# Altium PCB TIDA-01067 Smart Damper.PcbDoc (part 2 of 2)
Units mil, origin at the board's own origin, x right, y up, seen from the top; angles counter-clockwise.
Board outline 4000 x 3450 mil, 4 copper layers (Top Layer, Signal Layer 1, Signal Layer 2, Bottom Layer), stack 63 mil thick; 101 components, 44 nets, 285 pads, 617 vias.
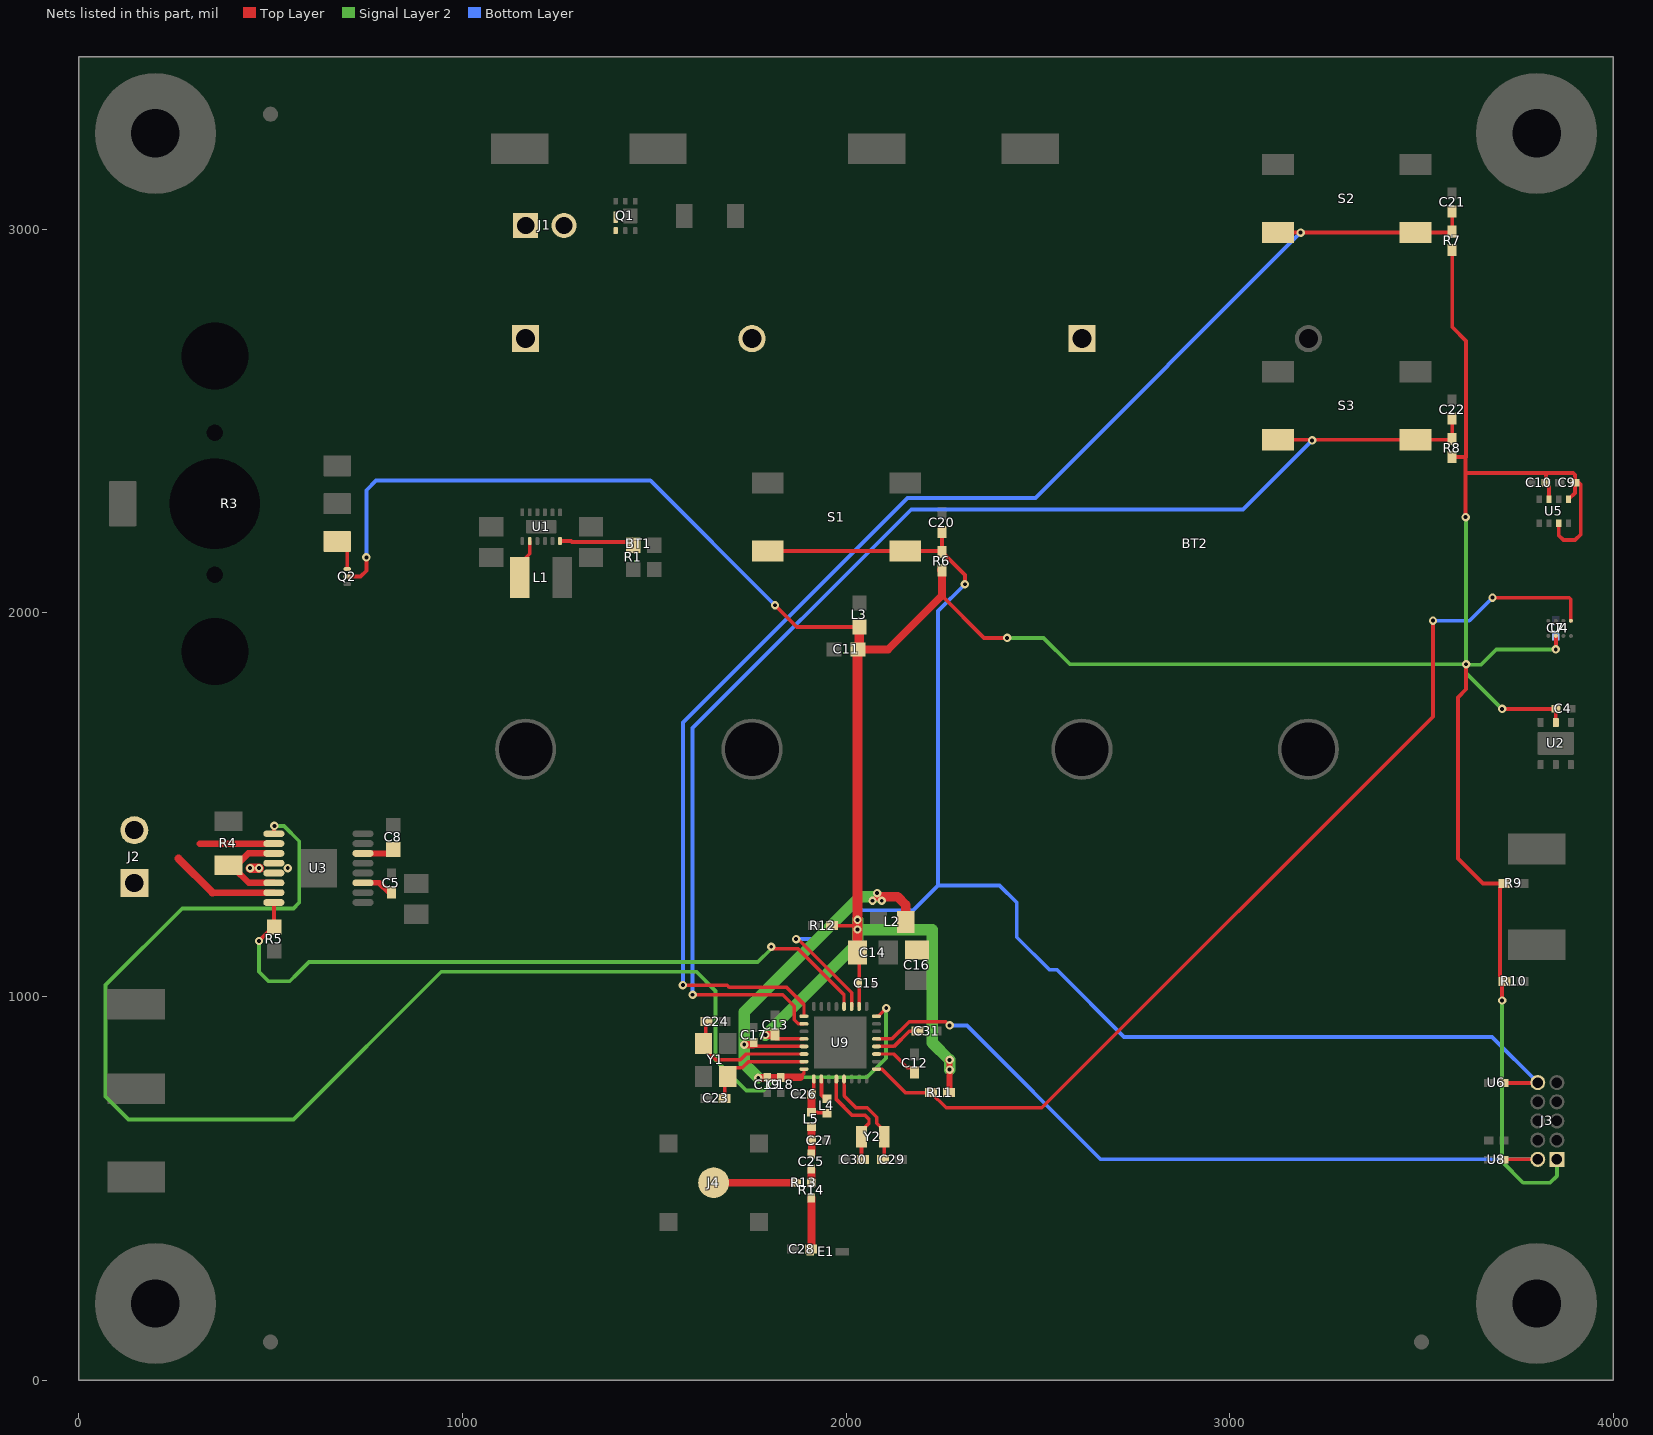
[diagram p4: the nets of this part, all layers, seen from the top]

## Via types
v1: diameter 22, hole 10, Top Layer to Bottom Layer, tented both sides, 560 vias
v2: diameter 19.68, hole 7.87, Top Layer to Bottom Layer, 29 vias
v3: diameter 22, hole 10, Top Layer to Bottom Layer, 27 vias
v4: diameter 19, hole 8, Top Layer to Bottom Layer, tented both sides, 1 vias

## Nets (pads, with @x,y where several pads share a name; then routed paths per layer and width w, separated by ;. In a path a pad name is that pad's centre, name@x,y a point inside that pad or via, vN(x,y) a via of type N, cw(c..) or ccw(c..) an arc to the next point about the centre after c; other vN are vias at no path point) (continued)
JTAG_TMS: J3.2 U8.1 U9.13 | length 1979.2
  Top Layer w9: U9.13@2079.49,889.84 2119.84,889.84 2165,935 2260,935 v1(2270,925)
  Top Layer w10: U8.1@3714.69,576 J3.2@3803,576
  Bottom Layer w10: v1(2270,925) 2315,925 2664,576 J3.2@3803,576
NDRDY_HDC: R11.1 U4.D2 U9.9 | length 2606.9
  Top Layer w9: U9.9@2079.49,811.1 2093.9,811.1 2155,750 R11.1@2221.38,750 2261.38,710 2510,710 3530,1730 ; v3(3685,2040) 3885,2040 3889.53,2035.47 U4.D2@3889.53,1979.69
  Top Layer w10: 3530,1730 v3(3530,1980)
  Bottom Layer w9: v3(3530,1980) 3625,1980 v3(3685,2040)
NetBT1_2: BT1.2 BT2.1
NetC5_1: C5.1 U3.11 | length 79.9
  Top Layer w15: U3.11@741.14,1296.61 783.39,1296.61 C5.1@810,1270
NetC8_1: C8.1 U3.14 | length 87.2
  Top Layer w15: U3.14@741.14,1373.39 811.89,1373.39 C8.1@823.5,1385
NetC23_2: C23.2 U9.31 Y1.3 | length 289.1
  Top Layer w9: Y1.3@1680,815 1730,815 1745.79,830.79 U9.31@1890.51,830.79 ; C23.2@1683.62,730 1683.62,783.82 Y1.3@1691.5,791.69 ; Y1.3@1695,810 Y1.3@1700,815
NetC24_2: C24.2 U9.30 Y1.1 | length 364.4
  Top Layer w9: Y1.1@1628.5,873.31 1628.5,866.5 1660,835 1725,835 1740.47,850.47 U9.30@1890.51,850.47 ; Y1.1@1628.5,878.31 Y1.1@1636.38,886.18 ; Y1.1@1635,870 C24.2@1635,935
NetC25_1: C25.1 R13.1 R14.1 | length 35.4
  Top Layer w10: R14.1@1904.68,515 R14.1@1905,515.32
  Top Layer w20: R14.1@1910,515.32 C25.1@1910,550.32
NetC25_2: C25.2 C27.1 L5.2 | length 71.9
  Top Layer w10: C25.2@1905,589.69 C25.2@1905.32,590 ; C27.1@1905,625.32 C27.1@1905.32,625
  Top Layer w20: C27.1@1910,625.32 L5.2@1910,661.3 ; C25.2@1910.32,590 C27.1@1910.32,625
NetC26_1: C26.1 L4.2 L5.1 U9.1 | length 140.2
  Top Layer w10: C26.1@1904.68,745 C26.1@1905,744.68 ; L5.1@1909.68,703.39 1905,698.7 1905.4,698.3 L4.2@1945,698.3 ; C26.1@1909.68,745 1916.1,745 U9.1@1916.1,785.51
  Top Layer w20: L5.1@1910,698.7 C26.1@1910,744.68
NetC28_2: C28.2 E1.2 R14.2 | length 133.9
  Top Layer w10: E1.2@1903.62,342 E1.2@1905,343.38
  Top Layer w20: E1.2@1910,343.38 R14.2@1910,475.31
NetC29_2: C29.2 U9.5 Y2.2 | length 271.6
  Top Layer w9: U9.5@1994.84,785.51 1994.84,768.7 1995,768.54 1995,741 2026,710 2055,710 2079.69,685.31 2079.69,670.31 Y2.2@2099.53,650.47
  Top Layer w10: Y2.2@2099.53,650.47 Y2.2@2099.53,635 2099.53,576.85 C29.2@2101.38,575
NetC30_1: C30.1 U9.4 Y2.1 | length 281.9
  Top Layer w9: U9.4@1975.16,785.51 1975.16,731.84 2016.69,690.31 2049.69,690.31 2060,680 2060,670 Y2.1@2040.47,650.47
  Top Layer w10: Y2.1@2035.16,640.32 Y2.1@2040.47,635 ; Y2.1@2040.47,650.47 Y2.1@2040.47,635 ; C30.1@2043.62,575 2040.47,578.15 Y2.1@2040.47,635
NetC31_2: C31.2 U9.12 | length 122
  Top Layer w9: U9.12@2079.49,870.16 2125.16,870.16 2165,910 C31.2@2185,910
NetJ1_2: J1.2 Q1.4 Q1.7
NetJ4_1: J4.1 R13.2 | length 210.3
  Top Layer w20: J4.1@1655,515 R13.2@1865.31,515
NetL1_1: L1.1 U1.2 | length 103.3
  Top Layer w9: L1.1@1150.14,2095 1150.14,2128.68 1175.93,2154.47 U1.2@1175.93,2187.6
NetL4_1: L4.1 U9.2 | length 55.6
  Top Layer w10: U9.2@1935.79,785.51 1935.79,742.91 L4.1@1945,733.7
NetQ2_3: Q2.3@700,2114.68 R3.1 | length 82.7
  Top Layer w10: R3.1@673.9,2186.57 700,2160.47 Q2.3@700,2114.68
NetR1_2: R1.2 U1.6 | length 205.4
  Top Layer w10: U1.6@1254.67,2187.6 1282.85,2187.6 1285.45,2185 1446.95,2185 R1.2@1455.45,2176.5
NetR4_2: R4.2 U3.3 U3.6 | length 260.1
  Top Layer w15: R4.2@385,1335.55 R4.2@404.45,1335.55
  Top Layer w17: U3.6@508.86,1296.61 443.39,1296.61 404.45,1335.55 442.28,1373.39 U3.3@508.86,1373.39
NFAULT: R5.1 U3.8 U9.20 | length 1855.3
  Top Layer w9: v1@1805,1125 1875,1125 1994.84,1005.16 U9.20@1994.84,974.49
  Top Layer w10: v1(470,1145) 501.5,1176.5 R5.1@510,1176.5 ; U3.8@508.86,1245.43 508.86,1177.64 R5.1@510,1176.5 ; R5.1@511.5,1175 R5.1@510,1176.5
  Signal Layer 2 w10: v1(470,1145) 470,1065 495,1040 550,1040 570,1060 600,1090 1770,1090 v1@1805,1125
  other v1: 1805,1130
NRESET: C20.2 J3.10 R6.1 S1.3 S1.4 U6.1 U9.19 | length 4011
  Top Layer w9: v1@1872.5,1152.5 2014.53,1010.47 U9.19@2014.53,974.49
  Top Layer w10: S1.3@1795.87,2161.42 S1.4@2154.13,2161.42 2247.2,2161.42 R6.1@2250,2158.62 ; C20.2@2250,2211.38 R6.1@2250,2158.62 ; v3(2310,2075) 2310,2098.62 R6.1@2250,2158.62 ; U6.1@3714.69,775 J3.10@3801.69,775
  Bottom Layer w10: v1(1870,1150) 1920,1150 1995,1225 2175,1225 2240,1290 ; v3(2310,2075) 2240,2005 2240,1290 ; J3.10@3803,776 3684,895 2725,895 2550,1070 2530,1070 2445,1155 2445,1245 2400,1290 2240,1290
NSLEEP: U3.1 U9.16 | length 3803.4
  Top Layer w9: U9.16@2079.49,948.9 2083.9,948.9 v1(2105,970)
  Top Layer w10: U3.1@508.86,1424.57 508.86,1443.86 v1(510,1445)
  Signal Layer 2 w10: v1(510,1445) 535,1445 575,1405 575,1245 560,1230 270,1230 70,1030 70,740 130,680 560,680 945,1065 1610,1065 1660,1015 1660,835 1740,755 1785,755 1820,790 2055,790 2104.49,839.49 v1@2104.49,974.49
NUSR_BTN1: C21.2 R7.1 S2.3 S2.4 U9.25 | length 3700.6
  Top Layer w9: v1@1580,1030 1690,1030 1695,1025 1845,1025 1890.51,979.49 U9.25@1890.51,948.9
  Top Layer w10: S2.3@3125.87,2991.42 v1(3185,2991.42) S2.4@3484.13,2991.42 3577.8,2991.42 R7.1@3580,2993.62 C21.2@3580,3046.38
  Bottom Layer w10: v1(1575,1030) v1@1575,1035 ; v1@1580,1030 v1@1575,1035 ; v1(3185,2991.42) 2493.58,2300 2160,2300 1575,1715 v1@1575,1035
NUSR_BTN2: C22.2 R8.1 S3.3 S3.4 U9.26 | length 3470.9
  Top Layer w9: v1(1600,1005) 1835,1005 1865,975 1865,940 1875.79,929.21 U9.26@1890.51,929.21
  Top Layer w10: S3.3@3125.87,2451.42 S3.4@3484.13,2451.42 3577.8,2451.42 R8.1@3580,2453.62 C22.2@3580,2506.38
  Bottom Layer w10: v1(1600,1005) 1600,1700 2170,2270 3035,2270 v1(3215,2450)
OUT1: J2.1 U3.2 U3.7 | length 478.5
  Top Layer w17: 316.02,1398.98 U3.2@508.86,1398.98 ; 348.98,1271.02 U3.7@508.86,1271.02
  Top Layer w20: 260,1360 348.98,1271.02
OUT2: J2.2 U3.4 U3.5 | length 23
  Top Layer w25: v1(447,1335) v1(470,1335)
  other v1: 545,1335
VBATT: BT1.1 J1.1
VDDR: C16.1 C17.2 C18.2 C19.1 L2.2 U9.29 U9.32 | length 1081.3
  Top Layer w9: C17.2@1758.62,875 1754.31,870.69 1754.84,870.16 U9.29@1890.51,870.16 ; v1@1770,790 v1(1771.38,788.62) ; 1880,790 1890.51,800.51 U9.32@1890.51,811.1
  Top Layer w20: v1(1735,875) C17.2@1758.62,875 ; v1(1771.38,788.62) 1840,788.62 ; 1845,790 1880,790
  Top Layer w25: v1@2085,1260 2135,1260 2155.43,1239.57 L2.2@2155.43,1195
  Signal Layer 2 w30: v1(1771.38,788.62) 1735,825 1735,960 2035,1260 v1@2085,1260
  other v1: 2069,1250 2093,1250 2081,1270
VDDS: C4.2 C7.2 C9.2 C10.2 C11.1 C12.2 C13.2 C14.1 C15.2 J3.1 L3.2 Q2.2@700,2095 R6.2 R7.2 R8.2 R9.2 R10.2 R11.2 R12.2 U2.5 U4.B1 U5.2 U5.6 U5.8 U9.11 U9.18 U9.28 | length 9933.6
  Top Layer w9: C13.2@1815,889.84 U9.28@1890.51,889.84 ; C14.1@2030,1128.43 2034.21,1124.21 2034.21,1119.21 U9.18@2034.21,974.49 ; U9.11@2079.49,850.47 2124.53,850.47 2160,815 C12.2@2170,815
  Top Layer w10: Q2.2@700,2095 735,2095 750,2110 v3(750,2145) ; C13.2@1813.62,900 C13.2@1815,901.38 ; v3(1815,2020) 1871.5,1963.5 L3.2@2035,1963.5 ; R12.2@1963.62,1185 2020,1185 v1(2030,1175) ; 2250,2045 2360,1935 v1(2420,1935) ; R6.2@2250,2111.38 R6.2@2251.38,2110 ; R8.2@3580,2406.38 3616.38,2406.38 3616.38,2708.62 3580,2745 R7.2@3580,2946.38 ; v3(3615,2250) 3615,2365 ; 3615,2405 3615,2365 ; v1(3616.38,1866.38) 3616.38,1801.38 3595,1780 3595,1360 3660,1295 R9.2@3716.38,1295 3705,1283.62 3705,1055 3716.38,1043.62 R10.2@3716.38,1040 3710,1033.62 v1(3710,990) ; v3(3710,1750) 3849.69,1750 3850,1749.69 U2.5@3850,1715.12 ; 3824.69,2364.69 C10.2@3824.69,2340 3824.69,2335 3832.2,2327.48 U5.6@3832.2,2296.5 ; v3(3850,1905) 3850.16,1905.16 U4.B1@3850.16,1940.32 ; U5.2@3855.31,2231.02 U5.2@3857.8,2233.5 3857.8,2202.2 3870,2190 3900,2190 3915,2205 3915,2335 3910,2340 C9.2@3899.69,2340 ; U5.8@3883.39,2296.5 3899.69,2312.8 C9.2@3899.69,2340 ; 3615,2365 3895,2365 3899.69,2360.31 C9.2@3899.69,2340
  Top Layer w15: v1@2265,835 2270,830 R11.2@2270,750
  Top Layer w20: v1(1790,900) C13.2@1813.62,900 ; C14.1@2030,1115 2034.21,1119.21 2035,1120 C14.1@2035,1125 ; C11.1@2035,1905 2110,1905 2250,2045 R6.2@2250,2111.38 ; R6.2@2250,2111.38 2250,2115 2247,2112 2249.38,2112 R6.2@2250,2111.38
  Top Layer w25: C14.1@2030,1128.43 v1(2030,1175) v1(2030,1200) C11.1@2030,1903.5 ; C11.1@2035,1905 L3.2@2035,1963.5
  Signal Layer 2 w10: v1(2420,1935) 2515,1935 2583.62,1866.38 v1(3616.38,1866.38) ; v3(3615,2250) 3616.38,2248.62 v1(3616.38,1866.38) ; v1(3710,990) 3710,570 3765,515 3835,515 3853,533 J3.1@3853,576 ; v3(3710,1750) 3616.38,1843.62 v1(3616.38,1866.38) ; v3(3850,1905) 3695,1905 3655,1865 3617.76,1865 v1(3616.38,1866.38)
  Signal Layer 2 w30: v1(1790,900) 2030,1140 v1(2030,1175) ; v1(2030,1200) v1(2030,1175) ; v1(2270,810) v1(2270,835) 2225,880 2225,1175 v1(2030,1175)
  Bottom Layer w10: v3(750,2145) 750,2320 775,2345 1490,2345 v3(1815,2020) ; v3(3850,1905) C7.2@3850,1940.31
pads on no net: BT1.3 BT1.4 BT2.3 BT2.4 FID1.1 FID2.1 FID3.1 H1.1 H2.1 H3.1 H4.1 H5.0 H6.0 H7.0 H8.0 J3.6 J3.7 J3.8 Q2.1@700,2074.33 Q2.2@700,2095 Q2.3@700,2115.67 R3. R3.4 SH-J1.0 U1.7 U1.13@1183.8,2225 U1.13@1227.11,2225 U2.3 U2.4 U2.7 U4.C2 U9.3 U9.8 U9.15
copper on no net:
  other v2: 3850,1640.32 3812.6,1660 3887.4,1660 3850,1679.68

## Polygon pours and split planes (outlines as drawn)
OUT2 on Signal Layer 2 "Top Layer-No Net" (solid, remove dead copper, pour order 48): 90,1495 245,1495 310,1495 340,1465 440,1465 560,1345 560,1315 560,1305 430,1305 265,1305 210,1360 205,1365 90,1365
GND on Top Layer "Top Layer-No Net" (solid, remove dead copper, pour order 46): 48.85,3398.85 3948.85,3398.85 3948.85,398.85 3948.85,368.85 2208.85,368.85 2198.85,358.85 2168.85,328.85 2158.85,328.85 1285.47,328.85 1249.47,364.85 1245.47,368.85 1198.85,368.85 48.85,368.85
OUT1 on Top Layer "Top Layer-No Net" (solid, remove dead copper, pour order 43): 165,1380 205,1420 340,1420 510,1420 520,1410 530,1400 530,1390 530,1255 520,1255 360,1255 340,1255 260,1255 105,1255 105,1380
6V on Top Layer "Top Layer-No Net" (solid, remove dead copper, pour order 42): 990.45,2190 1130.45,2190 1140.45,2200 1160.45,2200 1160.45,2175 1150.45,2165 1145.45,2160 1140.45,2160 1120.45,2160 1115.45,2155 1110.45,2150 1110.45,2110 990.45,2110
NetL1_1 on Top Layer "Top Layer-No Net" (solid, remove dead copper, pour order 39): 1170.45,2195 1170.45,2170 1160.45,2160 1150.45,2150 1145.45,2150 1130.45,2150 1125.45,2145 1125.45,2045 1175.45,2045 1175.45,2145 1180.45,2150 1180.45,2195
3V on Top Layer "Top Layer-No Net" (solid, remove dead copper, pour order 40): 1230.45,2195 1230.45,2165 1235.45,2160 1235.45,2045 1285.45,2045 1285.45,2075 1330.45,2120 1280.45,2170 1275.45,2170 1255.45,2170 1250.45,2175 1240.45,2185 1240.45,2195
6V on Top Layer "Top Layer-No Net" (solid, remove dead copper, pour order 45): 900,1265 900,1788.92 800,1888.92 800,2245 1415,2860 1415,3243.21 1605,3243.21 1605,2845 1018.21,2258.21 1018.21,2078.21 1070,2026.42 1070,1265
NetBT1_2 on Top Layer "Top Layer-No Net" (solid, remove dead copper, pour order 44): 1607.5,2750 1745,2887.5 2602.5,2887.5 2722.5,2805 2722.5,2645 2382.5,2645 2197.5,2645 2052.5,2645 1607.5,2645
NetC26_1 on Top Layer "Top Layer-No Net" (solid, remove dead copper, pour order 38): 1911,791 1911,782 1911,776 cw(c1891.17,782.83) 1903.02,765.53 ccw(c1910.05,756.95) 1899,756 1899,735 1921,735 1921,791
GND on Signal Layer 1 "Top Layer-No Net" (solid, remove dead copper, pour order 47): 50,3400 3950,3400 3950,400 3950,370 2210,370 2200,360 2170,330 2160,330 1286.62,330 1250.62,366 1246.62,370 1200,370 50,370
GND on Bottom Layer "Top Layer-No Net" (solid, remove dead copper, pour order 49): 50,3400 3950,3400 3950,400 3950,370 2210,370 2200,360 2170,330 2160,330 1286.62,330 1250.62,366 1246.62,370 1200,370 50,370

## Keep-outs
Keep-Out Layer:
  lines w10: -5,0 ccw(c0,0) 0,-5 ; -5,0 ccw(c0,0) 0,-5 ; -5,0 -5,3450 ; -5,3450 cw(c0,3450) 0,3455 ; -5,3450 cw(c0,3450) 0,3455 ; 0,-5 4000,-5 ; 0,3455 4000,3455 ; 4000,-5 ccw(c4000,0) 4005,0 ; 4000,-5 ccw(c4000,0) 4005,0 ; 4000,3455 cw(c4000,3450) 4005,3450 ; 4000,3455 cw(c4000,3450) 4005,3450 ; 4005,0 4005,3450
  text ".Layer_Name" at 577,-858.49 h60

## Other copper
Top Layer:
  rectangle net 3V: 1365.45,2100 1415.45,2130
  rectangle net VDDS: 2165,775 2275,820
  rectangle net 3V: 2010,2010 2060,2100
  region net GND: 1332.45,2207 1332.45,2243 1066.45,2243 1066.45,2207
  region net OUT2: 555,1355 460,1355 460,1315 555,1315
  region net 6V: 910,1370 850,1370 850,1270 910,1270
  region net 6V: 850,1335 810,1335 810,1300 850,1300
  rectangle net 6V: 1415,2965 1550,3265
  rectangle net NetJ1_2: 1225,2840 1405,3050
  rectangle net VBATT: 960,2665 1205,3055
  rectangle net 6V: 990.45,2100 1110.45,2170
  rectangle net 3V: 1270.45,2110 1415.45,2170
  region net VDDR: 2106,1240 2106,1281 2055,1281 2055,1240
  rectangle net VDDR: 2155,1135 2175,1180
  pour cut-out: 1180.45,2145 1320.45,2145 1320.45,2005 1180.45,2005
  region net GND: 1938.5,325.39 1938.5,365.39 2148.5,365.39 2188.5,405.39 2458.5,405.39 2458.5,365.39 2208.5,365.39 2168.5,325.39
  region net GND: 1875.62,362.81 1875.62,326 1290.62,326 1250.62,366 1000.62,366 1000.62,406 1260.62,406 1303.81,362.81
  pour cut-out: 2225,1105 2225,1000 2240,1000 2240,1105
  pour cut-out: 1575,3005 1580,3020 1580,2850 985,2255 985,2100 1015,2100 1018.21,2096.79 1018.21,2090 975,2090 975,2255 1575,2855
  text ".Layer_Name" at 577,-858.49 h60
Signal Layer 1:
  pour cut-out: 2005,990 2005.65,1194.35 2052.33,1241.03 2195,1240 2225,1210 2225,1020 2200,995 2110,995 2095,980 2095,970 2085,970 2085,985 2105,1005 2195,1005 2215,1025 2215,1205 2190,1230 2055,1230 2015.15,1190.15 2015.15,990
  text ".Layer_Name" at 577,-858.49 h60
Signal Layer 2:
  rectangle net 3V: 2010,2060 2060,2100
  rectangle net 3V: 1365.45,2095 1430.45,2165
  rectangle net VDDS: 2020,1160 2040,1210
  region net VDDR: 2105,1239 2105,1281 2058,1281 2058,1239
  text ".Layer_Name" at 577,-858.49 h60
Bottom Layer:
  pour cut-out: 2085,1080 2160,1080 2160,1010 2085,1010
  text ".Layer_Name" at 577,-858.49 h60
Multi-Layer:
  pour cut-out: 3725,2400 3995,2400 3995,1515 3725,1515

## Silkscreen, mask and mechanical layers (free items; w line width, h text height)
Top Overlay:
  region: 1335,825 1035,825 1035,725 1335,725
  text "6V" at 1435,3285 h60
  text "3V" at 2050,3285 h60
  text "GND" at 2425,3285 h60
  text "GND" at 1095,3280 h60
  text "User button 1" at 3135,2910 h60
  text "RESET" at 1885,2415 h60
  text "User button 2" at 3135,2365 h60
  text "OUT2" at 200,1535 h60
  text "SDA" at 3585,1410 h60
  text "OUT1" at 200,1155 h60
  text "SCL" at 3585,1125 h60
  text "IN2" at 255,965 h60
  text "JTAG" at 3760,835 h60
  text "IN1" at 255,740 h60
  text ".PRJ_Number" at 405,740 h100
  text ".PCB_Rev" at 895,740 h100
  text "-" at 976,740 h100
  text "GND" at 255,510 h60
  text ".Layer_Name" at 577,-858.49 h60
Bottom Overlay:
  text ".Layer_Name" at 577,-858.49 h60
Top Paste:
  text ".Layer_Name" at 577,-858.49 h60
Bottom Paste:
  text ".Layer_Name" at 577,-858.49 h60
Top Solder:
  text ".Layer_Name" at 577,-858.49 h60
  text ".Layer_Name" at 577,-858.49 h60
Bottom Solder:
  text ".Layer_Name" at 577,-858.49 h60
Drill Guide:
  text ".Layer_Name" at 577,-858.49 h60
M1 Board Outline:
  the board outline again, w10
  text ".Layer_Name" at 577,-858.49 h60
M2 Board Dimensions:
  rectangle: 0,-275 125,-150
  rectangle: 125,-400 500,-275
  lines w7: 0,-275 1000,-275 ; 125,-400 125,-150 ; 250,-400 250,-150 ; 500,-400 500,-150 ; 750,-400 750,-150 ; 0,-400 1000,-400 1000,-150 0,-150 0,-400
  text ".Layer_Name" at 577,-858.49 h60
M3 3D STEP Top:
  text ".Layer_Name" at 577,-858.49 h60
M4 3D STEP Bottom:
  text ".Layer_Name" at 577,-858.49 h60
M5 Assembly Top:
  lines w10: -292,-930.17 6308,-930.17 ; -292,-726.83 6310,-726.83 ; -292,-523.5 -292,-1133.5 3713,-1133.5 6310,-1133.5 6310,-523.5 -291.5,-523.5 -291.5,-1133.5 1284,-1133.5 ; 2173,-1133.5 2173,-523.5 ; 3440,-726.83 3440,-523.5 ; 4280,-726.83 4280,-523.5 ; 4902,-1140 4902,-937.17
  text "COMPONENTS MARKED 'DNP' SHOULD NOT BE POPULATED." at 1153.5,-318.5 h60
  text "ASSEMBLY VARIANT:" at 1153,-434 h60
  text ".VariantName" at 2189,-434 h60
  text "PCB VIEWED FROM TOP SIDE" at -228.5,-655.67 h60
  text "BOARD #:" at 2248,-655.67 h60
  text ".PRJ_Number" at 2793.5,-655.67 h60
  text "REV:" at 3638,-655.67 h60
  text ".PCB_Rev" at 3929.5,-655.67 h60
  text "SVN REV:" at 4476,-655.67 h60
  text ".VersionControl_RevNumber" at 4982,-655.67 h60
  text "TID #:" at 2248,-859 h60
  text ".TID" at 2793.5,-859 h60
  text "PLOT NAME =" at -228.5,-1064.34 h60
  text ".plot_File_Name" at 577,-1064.34 h60
  text "GENERATED    :" at 2250,-1064.34 h60
  text ".Print_Date" at 3119.5,-1064.34 h60
  text ".Print_Time" at 3848.5,-1064.34 h60
  text "TEXAS INSTRUMENTS" at 5113,-1064.34 h60
M6 Assembly Bottom:
  lines w10: -292.5,-727.33 6309.5,-727.33 ; -290.5,-930.67 6309.5,-930.67 ; 1115.5,-1140.5 1115.5,-937.67 ; 1737.5,-727.33 1737.5,-524 ; 2577.5,-727.33 2577.5,-524 ; 3844.5,-1134 3844.5,-524 ; 4733.5,-1134 6309,-1134 6309,-524 -292.5,-524 -292.5,-1134 2304.5,-1134 6309.5,-1134 6309.5,-524
  text "COMPONENTS MARKED 'DNP' SHOULD NOT BE POPULATED." at 6102,-318 h60
  text ".VariantName" at 5058,-434 h60
  text "ASSEMBLY VARIANT:" at 6097,-434 h60
  text ".VersionControl_RevNumber" at 1035.5,-656.17 h60
  text "SVN REV:" at 1541.5,-656.17 h60
  text ".PCB_Rev" at 2088,-656.17 h60
  text "REV:" at 2379.5,-656.17 h60
  text ".PRJ_Number" at 3224,-656.17 h60
  text "BOARD #:" at 3769.5,-656.17 h60
  text "PCB VIEWED FROM BOTTOM SIDE" at 6246,-656.17 h60
  text ".TID" at 3224,-859.5 h60
  text "TID #:" at 3769.5,-859.5 h60
  text "TEXAS INSTRUMENTS" at 904.5,-1064.84 h60
  text ".Print_Time" at 2169,-1064.84 h60
  text ".Print_Date" at 2898,-1064.84 h60
  text "GENERATED    :" at 3767.5,-1064.84 h60
  text ".plot_File_Name" at 5440.5,-1064.84 h60
  text "PLOT NAME =" at 6246,-1064.84 h60
M9 Title Sheet:
  drawing of 57 lines, arcs and shapes, not listed
  text "1" at 739.84,8036.5 h70
  text "2" at 3235.5,8036.5 h70
  text "3" at 5724.84,8036.5 h70
  text "4" at 8231.51,8036.5 h70
  text "5" at 10730.5,8036.5 h70
  text "6" at 13235.5,8036.5 h70
  text "A" at -416.5,6893.5 h70
  text "A" at 14383.5,6893.5 h70
  text "B" at -416.5,4513.5 h70
  text "B" at 14383.5,4513.5 h70
  text "C" at -416.5,2138.5 h70
  text "C" at 14383.5,2138.5 h70
  text "PROJECT TITLE:" at 11343.5,277.5 h45
  text ".PRJ_Title" at 11393.5,144.17 h70
  text "DESIGNED FOR:" at 11343.5,-23.5 h45
  text ".PRJ_Customer" at 11393.5,-163.5 h70
  text "D" at -416.5,-231.5 h70
  text "D" at 14383.5,-231.5 h70
  text "FILE NAME:" at 11343.5,-323.5 h45
  text ".PCB_File_Name_No_Path" at 11393.5,-443.5 h70
  text "Texas Instruments (TI) and/or its licensors do not warrant the accuracy or completeness of this specification" at 6374,-605.34 h45
  text "ENGINEER:" at 11343.5,-613.5 h45
  text "LAYOUT BY:" at 12848.5,-613.5 h45
  text "or any information contained therein. TI and/or its licensors do not warrant that this design will meet" at 6329.01,-718 h45
  text ".PRJ_Engineer" at 11393.5,-768.49 h70
  text ".PCB_Layout" at 12899,-768.49 h70
  text "the specifications, will be suitable for your application or fit for any particular purpose, or will operate in" at 6329.01,-830.67 h45
  text ".Layer_Name" at 577,-858.49 h60
  text "ALTIUM DESIGNER VERSION:" at 12848.5,-923.5 h45
  text "an implementation. TI and/or its licensors do not warrant that the design is production worthy. You should" at 6329.01,-943.33 h45
  text "completely validate and test your design implementation to confirm the system functionality for your application." at 6374,-1056 h45
  text ".print_Scale" at 11393.5,-1056.83 h70
  text ".Application_BuildNumber" at 12899,-1056.83 h70
  text "1" at 739.84,-1263.5 h70
  text "2" at 3235.5,-1263.5 h70
  text "3" at 5724.84,-1263.5 h70
  text "4" at 8231.51,-1263.5 h70
  text "5" at 10730.5,-1263.5 h70
  text "6" at 13235.5,-1263.5 h70
M10 Fab Notes:
  drawing of 173 lines, arcs and shapes, not listed
  text "DESIGN INFORMATION" at 12378.02,6201 h60
  text "MIN. TRACK WIDTH:" at 11733.46,6021 h60
  text "8" at 12829.7,6021 h60
  text "MIL" at 12984.46,6021 h60
  text "MIN. CLEARANCE:" at 11733.46,5889 h60
  text "8" at 12769.7,5889 h60
  text "MIL" at 12984.46,5889 h60
  text "MIN. VIA PAD SIZE:" at 11733.46,5757 h60
  text "19" at 12799.71,5757 h60
  text "MIL" at 12984.46,5757 h60
  text "0.05mm (2MIL)" at 12428.46,5615.29 h60
  text "MINIMUM ANNULAR RING" at 11404.23,5611 h60
  text "EXTERNAL" at 13136.46,5611 h60
  text "PER" at 11604.23,5493 h60
  text "IPC-D-275 CLASS 2 LEVEL C" at 11824.23,5493 h60
  text "MIL, HOLES" at 13312.46,5380.71 h60
  text "+/-" at 12920,5380 h60
  text "+/-" at 13774,5380 h60
  text "REGISTRATION TOLERANCES:" at 11404.23,5375 h60
  text "METAL" at 12604,5375 h60
  text "5" at 13180.2,5375 h60
  text "3" at 14013.2,5375 h60
  text "MIL" at 14129.46,5375 h60
  text "+/-" at 13774,5262 h60
  text "HOLE SIZE TOLERANCE (UNLESS OTHERWISE SPECIFIED):" at 11404.23,5257 h60
  text "3" at 14013.2,5257 h60
  text "MIL" at 14129.46,5257 h60
  text "MATERIAL:" at 11329.46,5047.54 h60
  text "FR-4 High Tg" at 12315.9,4907.21 h60
  text "FR-408" at 11750.46,4898.64 h60
  text "OTHER" at 13238.46,4898.64 h60
  text "X" at 12161,4895 h60
  text "62 MIL (1.6mm) +/-10%" at 12070.56,4735.92 h60
  text "THICKNESS:" at 11404.23,4731.64 h60
  text "X" at 11942.4,4731.64 h60
  text "OTHER" at 13355.46,4731.64 h60
  text "TOLERANCE:" at 11404.23,4573.64 h60
  text "X" at 12243.53,4573.64 h60
  text "ANSI IPC-6012 TYPE 3 CLASS 2" at 12430.48,4573.64 h60
  text "OTHER +/-" at 12430.46,4417.64 h60
  text "BOW & TWIST:" at 11404.23,4260.64 h60
  text "X" at 12243.53,4260.64 h60
  text "ANSI IPC-6012 TYPE 3 CLASS 2" at 12430.48,4260.64 h60
  text "OTHER +/-" at 12430.46,4102.13 h60
  text "DRILLING:" at 11329.46,3963.64 h60
  text "REFERENCE:" at 11404.23,3846.64 h60
  text "X" at 12052.46,3846.64 h60
  text "AS SHOWN" at 12239.46,3846.64 h60
  text "X" at 12953.46,3846.64 h60
  text "NC_DRILL FILES" at 13090.46,3846.64 h60
  text "PTH MIN COPPER THICKNESS:" at 11404.23,3688.64 h60
  text "X" at 12754.46,3688.64 h60
  text "1MIL" at 12891.46,3688.64 h60
  text "OTHER" at 13388.46,3688.64 h60
  text "BOARD FINISH:" at 11329.46,3529.64 h60
  text "SILKSCREEN:" at 11484.68,3411.64 h60
  text "X" at 12433.46,3411.64 h60
  text "TOP" at 12559.46,3411.64 h60
  text "X" at 12943.46,3411.64 h60
  text "BOTTOM" at 13070.46,3411.64 h60
  text "SILKSCREEN COLOR:" at 11484.68,3244.64 h60
  text "X" at 12432.42,3244.64 h60
  text "WHITE" at 12559.46,3244.64 h60
  text "OTHER" at 13070.46,3244.64 h60
  text "X" at 13150,3095 h60
  text "GREEN" at 12690.46,3085.44 h60
  text "OTHER" at 13308.46,3085.44 h60
  text "BLUE" at 13650,3085 h72.83
  text "SOLDER RESIST COLOR:" at 11484.68,3074.64 h60
  text "X" at 12563.42,2915.44 h60
  text "MATTE" at 12690.46,2915.44 h60
  text "SEMI-GLOSS" at 13308,2914.8 h60
  text "IMMERSION GOLD (ENIG)" at 12390.46,2726.92 h60
  text "ENEPIG" at 13728,2723.64 h60
  text "SURFACE FINISH:" at 11329.46,2722.64 h60
  text "X" at 12203.51,2722.64 h60
  text "IMM. TIN/SILVER OR EQUIV" at 11659,2565.64 h60
  text "OTHER" at 13090.46,2565.64 h60
  text "ARRAY/PANEL:" at 11329.46,2386.64 h60
  text "CUT AND TRIM PER M1 BOARD OUTLINE" at 12390.46,2382.35 h60
  text "N.C. ROUTE" at 12390.46,2230.64 h60
  text "X" at 13069.46,2230.64 h60
  text "V. SCORE" at 13256.46,2230.64 h60
  text "CERTIFICATION:" at 11329.46,2093.64 h60
  text "MATERIALS AND WORKMANSHIP FOR ALL PCBS" at 12054.46,2093.64 h60
  text "TO MEET OR EXCEED THE REQUIREMENTS OF:" at 12054.46,1995.64 h60
  text "X" at 11680.96,1859.13 h60
  text "ANSI IPC-A-600F CLASS ->" at 11819.96,1859.13 h60
  text "X" at 13459.02,1859.13 h60
  text "2" at 13577.96,1859.14 h60
  text "1" at 13262.96,1857.64 h60
  text "3" at 13931.96,1857.64 h60
  text "X" at 12495.02,1699.64 h60
  text "RoHS" at 12631.96,1699.64 h60
  text "OTHER" at 13276.36,1699.64 h60
  text "PER ORDER" at 13673.42,1699.64 h60
  text "ALL BOARDS MUST MEET OR EXCEED UL94-V0 REQUIREMENTS." at 11357,1534 h60
  text "PCB MUST BEAR THE UL94V-0 UL REGISTERED MATERIAL ID NUMBER" at 11357,1414 h60
  text "ADDITIONAL REQUIREMENTS:" at 11329.46,1240.64 h60
  text "MICROSECTION:" at 11404.23,1125.64 h60
  text "YES" at 12309.96,1125.64 h60
  text "REQUIRED" at 13171.46,969.49 h60
  text "BARE BOARD ELEC. TEST:" at 11404.23,966.64 h60
  text "NONE" at 12709.96,966.64 h60
  text "X" at 13044.46,966.64 h60
  text "PER ORDER" at 13763.46,966.64 h60
  text ".Layer_Name" at 577,-858.49 h60
M11 Gerber Information:
  lines w10: -292,-930.17 6308,-930.17 ; -292,-726.83 6310,-726.83 ; -292,-523.5 -292,-1133.5 3713,-1133.5 6310,-1133.5 6310,-523.5 -291.5,-523.5 -291.5,-1133.5 1284,-1133.5 ; 2173,-1133.5 2173,-523.5 ; 3440,-726.83 3440,-523.5 ; 4280,-726.83 4280,-523.5 ; 4902,-1140 4902,-937.17
  text "ALL ARTWORK VIEWED FROM TOP SIDE" at -228.5,-655.67 h60
  text "BOARD #:" at 2248,-655.67 h60
  text ".PRJ_Number" at 2793.5,-655.67 h60
  text "REV:" at 3638,-655.67 h60
  text ".PCB_Rev" at 3929.5,-655.67 h60
  text "SVN REV:" at 4476,-655.67 h60
  text ".VersionControl_RevNumber" at 4982,-655.67 h60
  text "LAYER NAME =" at -228.5,-858.49 h60
  text "TID #:" at 2248,-859 h60
  text ".TID" at 2793.5,-859 h60
  text "PLOT NAME =" at -228.5,-1064.34 h60
  text ".plot_File_Name" at 577,-1064.34 h60
  text "GENERATED    :" at 2250,-1064.34 h60
  text ".Print_Date" at 3119.5,-1064.34 h60
  text ".Print_Time" at 3848.5,-1064.34 h60
  text "TEXAS INSTRUMENTS" at 5113,-1064.34 h60
M12 Stackup:
  drawing of 295 lines, arcs and shapes, not listed
  text "Layer" at 9705,7745 h60
  text "Name" at 10114.91,7745 h60
  text "Material" at 11054.65,7745 h60
  text "Thickness" at 11914.42,7745 h60
  text "Constant" at 12564.26,7745 h60
  text "Board Layer Stack" at 13134.12,7745 h60
  text "1" at 9705,7625 h60
  text "Top Overlay" at 10114.91,7625 h60
  text "2" at 9705,7505 h60
  text "Top Solder" at 10114.91,7505 h60
  text "Solder Resist" at 11054.65,7505 h60
  text "0.40mil" at 11914.42,7505 h60
  text "3.5" at 12564.26,7505 h60
  text "3" at 9705,7385 h60
  text "Top Layer" at 10114.91,7385 h60
  text "Copper" at 11054.65,7385 h60
  text "1.40mil" at 11914.42,7385 h60
  text "4" at 9705,7265 h60
  text "Dielectric1" at 10114.91,7265 h60
  text "FR-4 High TG" at 11054.65,7265 h60
  text "6.90mil" at 11914.42,7265 h60
  text "4.2" at 12564.26,7265 h60
  text "5" at 9705,7145 h60
  text "Signal Layer 1" at 10114.91,7145 h60
  text "Copper" at 11054.65,7145 h60
  text "0.70mil" at 11914.42,7145 h60
  text "6" at 9705,7025 h60
  text "Dielectric 2" at 10114.91,7025 h60
  text "FR-4 High TG" at 11054.65,7025 h60
  text "45.00mil" at 11914.42,7025 h60
  text "4.2" at 12564.26,7025 h60
  text "7" at 9705,6905 h60
  text "Signal Layer 2" at 10114.91,6905 h60
  text "Copper" at 11054.65,6905 h60
  text "0.70mil" at 11914.42,6905 h60
  text "8" at 9705,6785 h60
  text "Dielectric 3" at 10114.91,6785 h60
  text "FR-4 High TG" at 11054.65,6785 h60
  text "6.90mil" at 11914.42,6785 h60
  text "4.2" at 12564.26,6785 h60
  text "9" at 9705,6665 h60
  text "Bottom Layer" at 10114.91,6665 h60
  text "Copper" at 11054.65,6665 h60
  text "1.40mil" at 11914.42,6665 h60
  text "10" at 9705,6545 h60
  text "Bottom Solder" at 10114.91,6545 h60
  text "Solder Resist" at 11054.65,6545 h60
  text "0.40mil" at 11914.42,6545 h60
  text "3.5" at 12564.26,6545 h60
  text "11" at 9705,6425 h60
  text "Bottom Overlay" at 10114.91,6425 h60
  text ".Layer_Name" at 577,-858.49 h60
M13 Component Bodies Top:
  text ".Layer_Name" at 577,-858.49 h60
M14 Component Bodies Bottom:
  text ".Layer_Name" at 577,-858.49 h60
M15 Courtyards Top:
  text ".Layer_Name" at 577,-858.49 h60
M16 Courtyards Bottom:
  text ".Layer_Name" at 577,-858.49 h60
Drill Drawing:
  lines w10: 4385.98,2004.16 4385.98,2017.94 4399.76,2031.72 4385.98,2045.5 4385.98,2059.28 4399.76,2059.28 4413.54,2045.5 4427.32,2059.28 4441.1,2059.28 4441.1,2045.5 4427.32,2031.72 4441.1,2017.94 4441.1,2004.16 4427.32,2004.16 4413.54,2017.94 4399.76,2004.16 4385.98,2004.16 ; 4385.98,2266 4399.76,2266 4399.76,2252.21 4427.32,2252.21 4427.32,2266 4441.1,2266 4441.1,2293.56 4427.32,2293.56 4427.32,2307.34 4399.76,2307.34 4399.76,2293.56 4385.98,2293.56 4385.98,2266 ; 4385.98,2431.36 4441.1,2431.36 4413.54,2376.24 4385.98,2431.36 ; 4385.98,3134.18 4399.76,3134.18 4399.76,3120.4 4427.32,3120.4 4427.32,3134.18 4441.1,3134.18 4441.1,3161.74 4427.32,3161.74 4427.32,3175.52 4399.76,3175.52 4399.76,3161.74 4385.98,3161.74 4385.98,3134.18 ; 4397,2015.19 4397,2023.45 4405.27,2031.72 4397,2039.99 4397,2048.26 4405.27,2048.26 4413.54,2039.99 4421.81,2048.26 4430.08,2048.26 4430.08,2039.99 4421.81,2031.72 4430.08,2023.45 4430.08,2015.19 4421.81,2015.19 4413.54,2023.45 4405.27,2015.19 4397,2015.19 ; 4397,2271.51 4405.27,2271.51 4405.27,2263.24 4421.81,2263.24 4421.81,2271.51 4430.08,2271.51 4430.08,2288.04 4421.81,2288.04 4421.81,2296.31 4405.27,2296.31 4405.27,2288.04 4397,2288.04 4397,2271.51 ; 4397,2420.34 4430.08,2420.34 4413.54,2387.27 4397,2420.34
  lines w12: 4336,1718.9 7408.72,1718.9 ; 4336,3331.25 7408.72,3331.25 ; 4673.36,1594.87 4673.36,3455.27 ; 5005.06,1594.87 5005.06,3455.27 ; 5640.91,1594.87 5640.91,3455.27 ; 5899.71,1594.87 5899.71,3455.27 ; 6274.46,1594.87 6274.46,3455.27 ; 6997,1594.87 6997,3455.27 ; 4336,1594.87 7408.72,1594.87 7408.72,3455.27 4336,3455.27 4336,1594.87
  text "Symbol" at 4410.42,3368.46 h72
  text "Quantity" at 4710.57,3368.46 h72
  text "Finished Hole Size" at 5042.26,3368.46 h72
  text "Plated" at 5678.12,3368.46 h72
  text "Hole Type" at 5936.92,3368.46 h72
  text "Drill Layer Pair" at 6311.67,3368.46 h72
  text "Tolerance" at 7034.21,3368.46 h72
  text "1" at 4710.57,3244.43 h60
  text "43.31mil (1.100mm)" at 5042.26,3244.43 h60
  text "NPTH" at 5678.12,3244.43 h60
  text "Round" at 5936.92,3244.43 h60
  text "Top Layer - Bottom Layer" at 6311.67,3244.43 h60
  text "I" at 4394.36,3234.44 h55.12
  text "2" at 4710.57,3120.4 h60
  text "175.00mil (4.445mm)" at 5042.26,3120.4 h60
  text "NPTH" at 5678.12,3120.4 h60
  text "Round" at 5936.92,3120.4 h60
  text "Top Layer - Bottom Layer" at 6311.67,3120.4 h60
  text "1" at 4710.57,2996.38 h60
  text "236.22mil (6.000mm)" at 5042.26,2996.38 h60
  text "NPTH" at 5678.12,2996.38 h60
  text "Round" at 5936.92,2996.38 h60
  text "Top Layer - Bottom Layer" at 6311.67,2996.38 h60
  text "H" at 4385.17,2986.38 h55.12
  text "29" at 4710.57,2872.35 h60
  text "7.87mil (0.200mm)" at 5042.26,2872.35 h60
  text "PTH" at 5678.12,2872.35 h60
  text "Round" at 5936.92,2872.35 h60
  text "Top Layer - Bottom Layer" at 6311.67,2872.35 h60
  text "E" at 4385.17,2862.36 h55.12
  text "1" at 4710.57,2748.32 h60
  text "8.00mil (0.203mm)" at 5042.26,2748.32 h60
  text "PTH" at 5678.12,2748.32 h60
  text "Round" at 5936.92,2748.32 h60
  text "Top Layer - Bottom Layer" at 6311.67,2748.32 h60
  text "G" at 4385.17,2738.33 h55.12
  text "587" at 4710.57,2624.3 h60
  text "10.00mil (0.254mm)" at 5042.26,2624.3 h60
  text "PTH" at 5678.12,2624.3 h60
  text "Round" at 5936.92,2624.3 h60
  text "Top Layer - Bottom Layer" at 6311.67,2624.3 h60
  text "F" at 4385.17,2614.3 h55.12
  text "10" at 4710.57,2500.27 h60
  text "27.56mil (0.700mm)" at 5042.26,2500.27 h60
  text "PTH" at 5678.12,2500.27 h60
  text "Round" at 5936.92,2500.27 h60
  text "Top Layer - Bottom Layer" at 6311.67,2500.27 h60
  text "D" at 4385.17,2490.28 h55.12
  text "2" at 4710.57,2376.24 h60
  text "45.28mil (1.150mm)" at 5042.26,2376.24 h60
  text "PTH" at 5678.12,2376.24 h60
  text "Round" at 5936.92,2376.24 h60
  text "Top Layer - Bottom Layer" at 6311.67,2376.24 h60
  text "2" at 4710.57,2252.21 h60
  text "47.24mil (1.200mm)" at 5042.26,2252.21 h60
  text "PTH" at 5678.12,2252.21 h60
  text "Round" at 5936.92,2252.21 h60
  text "Top Layer - Bottom Layer" at 6311.67,2252.21 h60
  text "4" at 4710.57,2128.19 h60
  text "50.00mil (1.270mm)" at 5042.26,2128.19 h60
  text "PTH" at 5678.12,2128.19 h60
  text "Round" at 5936.92,2128.19 h60
  text "Top Layer - Bottom Layer" at 6311.67,2128.19 h60
  text "C" at 4385.17,2118.2 h55.12
  text "4" at 4710.57,2004.16 h60
  text "125.98mil (3.200mm)" at 5042.26,2004.16 h60
  text "PTH" at 5678.12,2004.16 h60
  text "Round" at 5936.92,2004.16 h60
  text "Top Layer - Bottom Layer" at 6311.67,2004.16 h60
  text "4" at 4710.57,1880.13 h60
  text "139.76mil (3.550mm)" at 5042.26,1880.13 h60
  text "PTH" at 5678.12,1880.13 h60
  text "Round" at 5936.92,1880.13 h60
  text "Top Layer - Bottom Layer" at 6311.67,1880.13 h60
  text "B" at 4385.17,1870.14 h55.12
  text "1" at 4710.57,1756.11 h60
  text "43.31mil (1.100mm)" at 5042.26,1756.11 h60
  text "NPTH" at 5678.12,1756.11 h60
  text "Slot" at 5936.92,1756.11 h60
  text "Top Layer - Bottom Layer" at 6311.67,1756.11 h60
  text "J" at 4385.17,1746.12 h55.12
  text "648 Total" at 4710.57,1632.08 h60
  text "Slot definitions :" at 4410.42,1545.26 h60
  text "Routed Path Length" at 4859.86,1545.26 h60
  text "= Calculated from tool start centre position to tool end centre position." at 5398.21,1545.26 h60
  text "Hole Length" at 4859.86,1495.65 h60
  text "= Routed Path Length + Tool Size = Slot length as defined in the PCB layout" at 5198.91,1495.65 h60
  text ".Layer_Name" at 577,-858.49 h60
M17 Embedded Cavity:
  text ".Layer_Name" at 577,-858.49 h60
M18 Embedded Assembly:
  text ".Layer_Name" at 577,-858.49 h60
M19 Embedded Keepout:
  text ".Layer_Name" at 577,-858.49 h60

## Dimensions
0,-400 to 1000,-400 on M2 Board Dimensions
0,0 to 4000,0 on M2 Board Dimensions
0,0 to 0,3450 on M2 Board Dimensions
